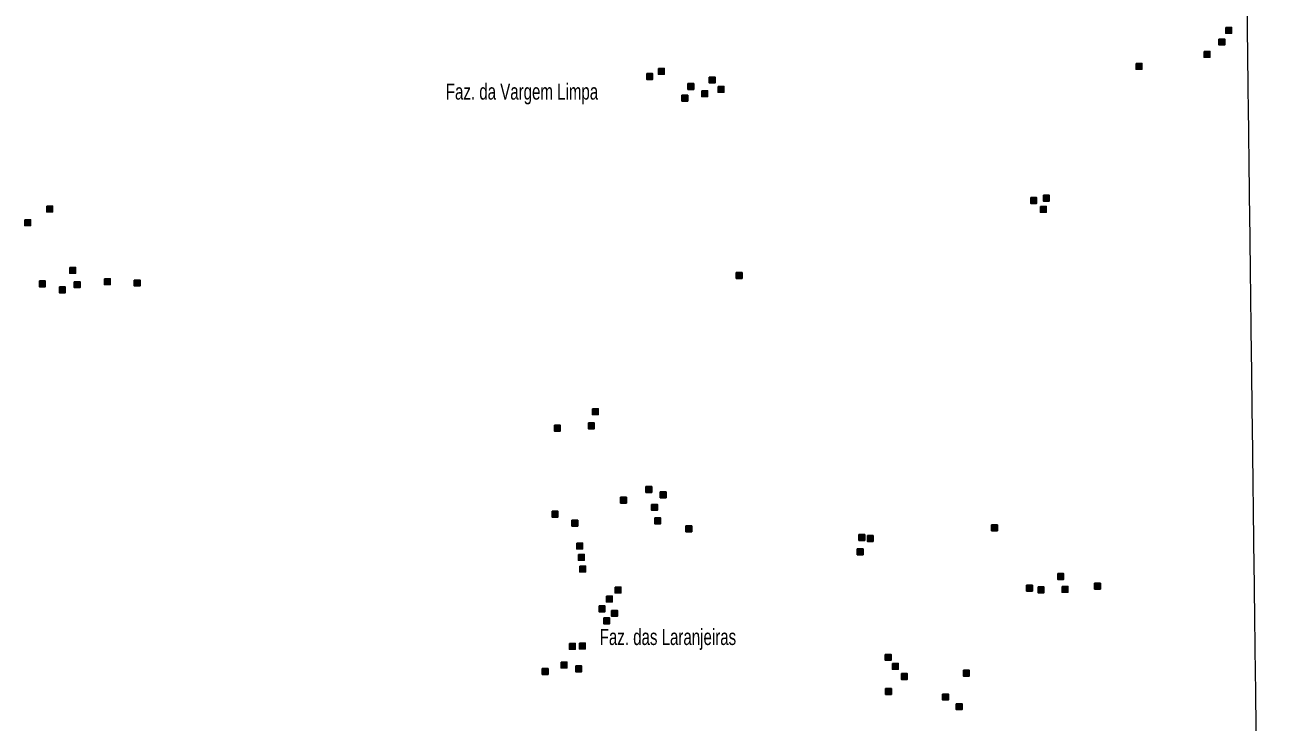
# Model space of a CAD drawing. Extents: x 265.7 to 292.1, y 7676.2 to 7704.2.
# Drawn here: x 285.94 to 292.1, y 7679.73 to 7683.19 of the extents above; entities that cross this region are included whole.
import ezdxf

# ---------------------------------------------------------------- set-up
doc = ezdxf.new("R2010")
doc.units = 0
doc.header["$LTSCALE"] = 0.032
doc.layers.add('2', color=7, linetype='Continuous', lineweight=25)
doc.layers.add('63', color=7, linetype='Continuous', lineweight=13)
doc.layers.add('61', color=7, linetype='Continuous')

msp = doc.modelspace()

# ---------------------------------------------------------------- hatches: boundary and pattern name
at = {"layer": '2'}
for points in [[(291.9108, 7683.1808), (291.9398, 7683.1808), (291.9398, 7683.1518), (291.9108, 7683.1518)], [(291.8769, 7683.1234), (291.9059, 7683.1234), (291.9059, 7683.0944), (291.8769, 7683.0944)], [(291.8035, 7683.0614), (291.8325, 7683.0614), (291.8325, 7683.0324), (291.8035, 7683.0324)], [(291.4653, 7683.0024), (291.4943, 7683.0024), (291.4943, 7682.9734), (291.4653, 7682.9734)], [(289.032, 7682.9516), (289.061, 7682.9516), (289.061, 7682.9226), (289.032, 7682.9226)], [(289.0902, 7682.9775), (289.1192, 7682.9775), (289.1192, 7682.9485), (289.0902, 7682.9485)], [(289.3428, 7682.9338), (289.3718, 7682.9338), (289.3718, 7682.9048), (289.3428, 7682.9048)], [(289.237, 7682.9015), (289.266, 7682.9015), (289.266, 7682.8725), (289.237, 7682.8725)], [(289.3056, 7682.866), (289.3346, 7682.866), (289.3346, 7682.837), (289.3056, 7682.837)], [(289.3863, 7682.8877), (289.4153, 7682.8877), (289.4153, 7682.8587), (289.3863, 7682.8587)], [(289.2071, 7682.8441), (289.2361, 7682.8441), (289.2361, 7682.8151), (289.2071, 7682.8151)], [(290.9415, 7682.3349), (290.9705, 7682.3349), (290.9705, 7682.3059), (290.9415, 7682.3059)], [(291.0045, 7682.3463), (291.0335, 7682.3463), (291.0335, 7682.3173), (291.0045, 7682.3173)], [(286.0484, 7682.2929), (286.0774, 7682.2929), (286.0774, 7682.2639), (286.0484, 7682.2639)], [(290.9891, 7682.2914), (291.0181, 7682.2914), (291.0181, 7682.2624), (290.9891, 7682.2624)], [(285.9394, 7682.2252), (285.9684, 7682.2252), (285.9684, 7682.1962), (285.9394, 7682.1962)], [(286.163, 7681.988), (286.192, 7681.988), (286.192, 7681.959), (286.163, 7681.959)], [(286.3357, 7681.9315), (286.3647, 7681.9315), (286.3647, 7681.9025), (286.3357, 7681.9025)], [(289.4768, 7681.9621), (289.5058, 7681.9621), (289.5058, 7681.9331), (289.4768, 7681.9331)], [(286.0121, 7681.921), (286.0411, 7681.921), (286.0411, 7681.892), (286.0121, 7681.892)], [(286.1113, 7681.891), (286.1403, 7681.891), (286.1403, 7681.862), (286.1113, 7681.862)], [(286.1856, 7681.9169), (286.2146, 7681.9169), (286.2146, 7681.8879), (286.1856, 7681.8879)], [(286.4833, 7681.9249), (286.5123, 7681.9249), (286.5123, 7681.8959), (286.4833, 7681.8959)], [(288.7616, 7681.285), (288.7906, 7681.285), (288.7906, 7681.256), (288.7616, 7681.256)], [(288.5729, 7681.2035), (288.6019, 7681.2035), (288.6019, 7681.1745), (288.5729, 7681.1745)], [(288.7422, 7681.2148), (288.7712, 7681.2148), (288.7712, 7681.1858), (288.7422, 7681.1858)], [(289.028, 7680.8984), (289.057, 7680.8984), (289.057, 7680.8694), (289.028, 7680.8694)], [(288.9021, 7680.8452), (288.9311, 7680.8452), (288.9311, 7680.8162), (288.9021, 7680.8162)], [(289.099, 7680.8718), (289.128, 7680.8718), (289.128, 7680.8428), (289.099, 7680.8428)], [(288.5614, 7680.7758), (288.5904, 7680.7758), (288.5904, 7680.7468), (288.5614, 7680.7468)], [(289.0561, 7680.8097), (289.0851, 7680.8097), (289.0851, 7680.7807), (289.0561, 7680.7807)], [(288.66, 7680.7306), (288.689, 7680.7306), (288.689, 7680.7016), (288.66, 7680.7016)], [(289.0716, 7680.7426), (289.1006, 7680.7426), (289.1006, 7680.7136), (289.0716, 7680.7136)], [(289.2266, 7680.7031), (289.2556, 7680.7031), (289.2556, 7680.6741), (289.2266, 7680.6741)], [(290.747, 7680.708), (290.776, 7680.708), (290.776, 7680.679), (290.747, 7680.679)], [(290.0868, 7680.6595), (290.1158, 7680.6595), (290.1158, 7680.6305), (290.0868, 7680.6305)], [(290.1288, 7680.6546), (290.1578, 7680.6546), (290.1578, 7680.6256), (290.1288, 7680.6256)], [(288.6841, 7680.6175), (288.7131, 7680.6175), (288.7131, 7680.5885), (288.6841, 7680.5885)], [(290.0788, 7680.5885), (290.1078, 7680.5885), (290.1078, 7680.5595), (290.0788, 7680.5595)], [(288.6922, 7680.5611), (288.7212, 7680.5611), (288.7212, 7680.5321), (288.6922, 7680.5321)], [(288.6987, 7680.503), (288.7277, 7680.503), (288.7277, 7680.474), (288.6987, 7680.474)], [(291.0754, 7680.4659), (291.1044, 7680.4659), (291.1044, 7680.4369), (291.0754, 7680.4369)], [(288.8746, 7680.3989), (288.9036, 7680.3989), (288.9036, 7680.3699), (288.8746, 7680.3699)], [(290.9205, 7680.4077), (290.9495, 7680.4077), (290.9495, 7680.3787), (290.9205, 7680.3787)], [(290.9778, 7680.3997), (291.0068, 7680.3997), (291.0068, 7680.3707), (290.9778, 7680.3707)], [(291.0973, 7680.4021), (291.1263, 7680.4021), (291.1263, 7680.3731), (291.0973, 7680.3731)], [(291.2587, 7680.4174), (291.2877, 7680.4174), (291.2877, 7680.3884), (291.2587, 7680.3884)], [(288.8318, 7680.3537), (288.8608, 7680.3537), (288.8608, 7680.3247), (288.8318, 7680.3247)], [(288.7948, 7680.3053), (288.8238, 7680.3053), (288.8238, 7680.2763), (288.7948, 7680.2763)], [(288.8569, 7680.2826), (288.8859, 7680.2826), (288.8859, 7680.2536), (288.8569, 7680.2536)], [(288.8181, 7680.2455), (288.8471, 7680.2455), (288.8471, 7680.2165), (288.8181, 7680.2165)], [(288.6471, 7680.1188), (288.6761, 7680.1188), (288.6761, 7680.0898), (288.6471, 7680.0898)], [(288.6971, 7680.1205), (288.7261, 7680.1205), (288.7261, 7680.0915), (288.6971, 7680.0915)], [(288.6064, 7680.0261), (288.6354, 7680.0261), (288.6354, 7679.9971), (288.6064, 7679.9971)], [(290.2175, 7680.0639), (290.2465, 7680.0639), (290.2465, 7680.0349), (290.2175, 7680.0349)], [(288.5123, 7679.9937), (288.5413, 7679.9937), (288.5413, 7679.9647), (288.5123, 7679.9647)], [(288.6791, 7680.007), (288.7081, 7680.007), (288.7081, 7679.978), (288.6791, 7679.978)], [(290.2537, 7680.0191), (290.2827, 7680.0191), (290.2827, 7679.9901), (290.2537, 7679.9901)], [(290.2984, 7679.9684), (290.3274, 7679.9684), (290.3274, 7679.9394), (290.2984, 7679.9394)], [(290.6065, 7679.9851), (290.6355, 7679.9851), (290.6355, 7679.9561), (290.6065, 7679.9561)], [(290.2192, 7679.8937), (290.2482, 7679.8937), (290.2482, 7679.8647), (290.2192, 7679.8647)], [(290.5032, 7679.867), (290.5322, 7679.867), (290.5322, 7679.838), (290.5032, 7679.838)], [(290.571, 7679.8186), (290.6, 7679.8186), (290.6, 7679.7896), (290.571, 7679.7896)]]:
    msp.add_hatch(color=256, dxfattribs=at).paths.add_polyline_path(points)

# ---------------------------------------------------------------- linework, layer by layer
for points in [[(291.9108, 7683.1808), (291.9398, 7683.1808), (291.9398, 7683.1518), (291.9108, 7683.1518)], [(291.8769, 7683.1234), (291.9059, 7683.1234), (291.9059, 7683.0944), (291.8769, 7683.0944)], [(291.8035, 7683.0614), (291.8325, 7683.0614), (291.8325, 7683.0324), (291.8035, 7683.0324)], [(291.4653, 7683.0024), (291.4943, 7683.0024), (291.4943, 7682.9734), (291.4653, 7682.9734)], [(289.032, 7682.9516), (289.061, 7682.9516), (289.061, 7682.9226), (289.032, 7682.9226)], [(289.0902, 7682.9775), (289.1192, 7682.9775), (289.1192, 7682.9485), (289.0902, 7682.9485)], [(289.3428, 7682.9338), (289.3718, 7682.9338), (289.3718, 7682.9048), (289.3428, 7682.9048)], [(289.237, 7682.9015), (289.266, 7682.9015), (289.266, 7682.8725), (289.237, 7682.8725)], [(289.3056, 7682.866), (289.3346, 7682.866), (289.3346, 7682.837), (289.3056, 7682.837)], [(289.3863, 7682.8877), (289.4153, 7682.8877), (289.4153, 7682.8587), (289.3863, 7682.8587)], [(289.2071, 7682.8441), (289.2361, 7682.8441), (289.2361, 7682.8151), (289.2071, 7682.8151)], [(290.9415, 7682.3349), (290.9705, 7682.3349), (290.9705, 7682.3059), (290.9415, 7682.3059)], [(291.0045, 7682.3463), (291.0335, 7682.3463), (291.0335, 7682.3173), (291.0045, 7682.3173)], [(286.0484, 7682.2929), (286.0774, 7682.2929), (286.0774, 7682.2639), (286.0484, 7682.2639)], [(290.9891, 7682.2914), (291.0181, 7682.2914), (291.0181, 7682.2624), (290.9891, 7682.2624)], [(285.9394, 7682.2252), (285.9684, 7682.2252), (285.9684, 7682.1962), (285.9394, 7682.1962)], [(286.163, 7681.988), (286.192, 7681.988), (286.192, 7681.959), (286.163, 7681.959)], [(286.3357, 7681.9315), (286.3647, 7681.9315), (286.3647, 7681.9025), (286.3357, 7681.9025)], [(289.4768, 7681.9621), (289.5058, 7681.9621), (289.5058, 7681.9331), (289.4768, 7681.9331)], [(286.0121, 7681.921), (286.0411, 7681.921), (286.0411, 7681.892), (286.0121, 7681.892)], [(286.1113, 7681.891), (286.1403, 7681.891), (286.1403, 7681.862), (286.1113, 7681.862)], [(286.1856, 7681.9169), (286.2146, 7681.9169), (286.2146, 7681.8879), (286.1856, 7681.8879)], [(286.4833, 7681.9249), (286.5123, 7681.9249), (286.5123, 7681.8959), (286.4833, 7681.8959)], [(288.7616, 7681.285), (288.7906, 7681.285), (288.7906, 7681.256), (288.7616, 7681.256)], [(288.5729, 7681.2035), (288.6019, 7681.2035), (288.6019, 7681.1745), (288.5729, 7681.1745)], [(288.7422, 7681.2148), (288.7712, 7681.2148), (288.7712, 7681.1858), (288.7422, 7681.1858)], [(289.028, 7680.8984), (289.057, 7680.8984), (289.057, 7680.8694), (289.028, 7680.8694)], [(288.9021, 7680.8452), (288.9311, 7680.8452), (288.9311, 7680.8162), (288.9021, 7680.8162)], [(289.099, 7680.8718), (289.128, 7680.8718), (289.128, 7680.8428), (289.099, 7680.8428)], [(288.5614, 7680.7758), (288.5904, 7680.7758), (288.5904, 7680.7468), (288.5614, 7680.7468)], [(289.0561, 7680.8097), (289.0851, 7680.8097), (289.0851, 7680.7807), (289.0561, 7680.7807)], [(288.66, 7680.7306), (288.689, 7680.7306), (288.689, 7680.7016), (288.66, 7680.7016)], [(289.0716, 7680.7426), (289.1006, 7680.7426), (289.1006, 7680.7136), (289.0716, 7680.7136)], [(289.2266, 7680.7031), (289.2556, 7680.7031), (289.2556, 7680.6741), (289.2266, 7680.6741)], [(290.747, 7680.708), (290.776, 7680.708), (290.776, 7680.679), (290.747, 7680.679)], [(290.0868, 7680.6595), (290.1158, 7680.6595), (290.1158, 7680.6305), (290.0868, 7680.6305)], [(290.1288, 7680.6546), (290.1578, 7680.6546), (290.1578, 7680.6256), (290.1288, 7680.6256)], [(288.6841, 7680.6175), (288.7131, 7680.6175), (288.7131, 7680.5885), (288.6841, 7680.5885)], [(290.0788, 7680.5885), (290.1078, 7680.5885), (290.1078, 7680.5595), (290.0788, 7680.5595)], [(288.6922, 7680.5611), (288.7212, 7680.5611), (288.7212, 7680.5321), (288.6922, 7680.5321)], [(288.6987, 7680.503), (288.7277, 7680.503), (288.7277, 7680.474), (288.6987, 7680.474)], [(291.0754, 7680.4659), (291.1044, 7680.4659), (291.1044, 7680.4369), (291.0754, 7680.4369)], [(288.8746, 7680.3989), (288.9036, 7680.3989), (288.9036, 7680.3699), (288.8746, 7680.3699)], [(290.9205, 7680.4077), (290.9495, 7680.4077), (290.9495, 7680.3787), (290.9205, 7680.3787)], [(290.9778, 7680.3997), (291.0068, 7680.3997), (291.0068, 7680.3707), (290.9778, 7680.3707)], [(291.0973, 7680.4021), (291.1263, 7680.4021), (291.1263, 7680.3731), (291.0973, 7680.3731)], [(291.2587, 7680.4174), (291.2877, 7680.4174), (291.2877, 7680.3884), (291.2587, 7680.3884)], [(288.8318, 7680.3537), (288.8608, 7680.3537), (288.8608, 7680.3247), (288.8318, 7680.3247)], [(288.7948, 7680.3053), (288.8238, 7680.3053), (288.8238, 7680.2763), (288.7948, 7680.2763)], [(288.8569, 7680.2826), (288.8859, 7680.2826), (288.8859, 7680.2536), (288.8569, 7680.2536)], [(288.8181, 7680.2455), (288.8471, 7680.2455), (288.8471, 7680.2165), (288.8181, 7680.2165)], [(288.6471, 7680.1188), (288.6761, 7680.1188), (288.6761, 7680.0898), (288.6471, 7680.0898)], [(288.6971, 7680.1205), (288.7261, 7680.1205), (288.7261, 7680.0915), (288.6971, 7680.0915)], [(288.6064, 7680.0261), (288.6354, 7680.0261), (288.6354, 7679.9971), (288.6064, 7679.9971)], [(290.2175, 7680.0639), (290.2465, 7680.0639), (290.2465, 7680.0349), (290.2175, 7680.0349)], [(288.5123, 7679.9937), (288.5413, 7679.9937), (288.5413, 7679.9647), (288.5123, 7679.9647)], [(288.6791, 7680.007), (288.7081, 7680.007), (288.7081, 7679.978), (288.6791, 7679.978)], [(290.2537, 7680.0191), (290.2827, 7680.0191), (290.2827, 7679.9901), (290.2537, 7679.9901)], [(290.2984, 7679.9684), (290.3274, 7679.9684), (290.3274, 7679.9394), (290.2984, 7679.9394)], [(290.6065, 7679.9851), (290.6355, 7679.9851), (290.6355, 7679.9561), (290.6065, 7679.9561)], [(290.2192, 7679.8937), (290.2482, 7679.8937), (290.2482, 7679.8647), (290.2192, 7679.8647)], [(290.5032, 7679.867), (290.5322, 7679.867), (290.5322, 7679.838), (290.5032, 7679.838)], [(290.571, 7679.8186), (290.6, 7679.8186), (290.6, 7679.7896), (290.571, 7679.7896)]]:
    msp.add_lwpolyline(points, close=True, dxfattribs=at)
at = {"layer": '63'}
msp.add_spline([(292.1022, 7676.5221), (292.0951, 7677.087), (292.088, 7677.6519), (292.081, 7678.2168), (292.0739, 7678.7818), (292.0668, 7679.3467), (292.0598, 7679.9116), (292.0527, 7680.4765), (292.0457, 7681.0414), (292.0386, 7681.6064), (292.0316, 7682.1713), (292.0245, 7682.7362), (292.0175, 7683.3011), (292.0104, 7683.866), (292.0034, 7684.431), (291.9963, 7684.9959), (291.9893, 7685.5608), (291.9822, 7686.1257), (291.9752, 7686.6906), (291.9681, 7687.2556), (291.9611, 7687.8205), (291.9541, 7688.3854), (291.947, 7688.9503), (291.94, 7689.5152), (291.933, 7690.0801), (291.9259, 7690.6451), (291.9189, 7691.21), (291.9119, 7691.7749), (291.9049, 7692.3398), (291.8978, 7692.9047), (291.8908, 7693.4696), (291.8838, 7694.0345), (291.8768, 7694.5995), (291.8698, 7695.1644), (291.8628, 7695.7293), (291.8557, 7696.2942), (291.8487, 7696.8591), (291.8417, 7697.424), (291.8347, 7697.9889), (291.8277, 7698.5539), (291.8207, 7699.1188), (291.8137, 7699.6837), (291.8067, 7700.2486), (291.7997, 7700.8135), (291.7927, 7701.3784), (291.7857, 7701.9433), (291.7787, 7702.5082), (291.7717, 7703.0731), (291.7647, 7703.638), (291.7577, 7704.203)], degree=3, dxfattribs=at)

# ---------------------------------------------------------------- texts
at = {"layer": '61', "width": 0.7}
for s, p in [('Faz. da Vargem Limpa', (288.0329, 7682.822)), ('Faz. das Laranjeiras', (288.798, 7680.1106))]:
    msp.add_text(s, height=0.08, dxfattribs=at).set_placement(p)

doc.saveas('drawing.dxf')
